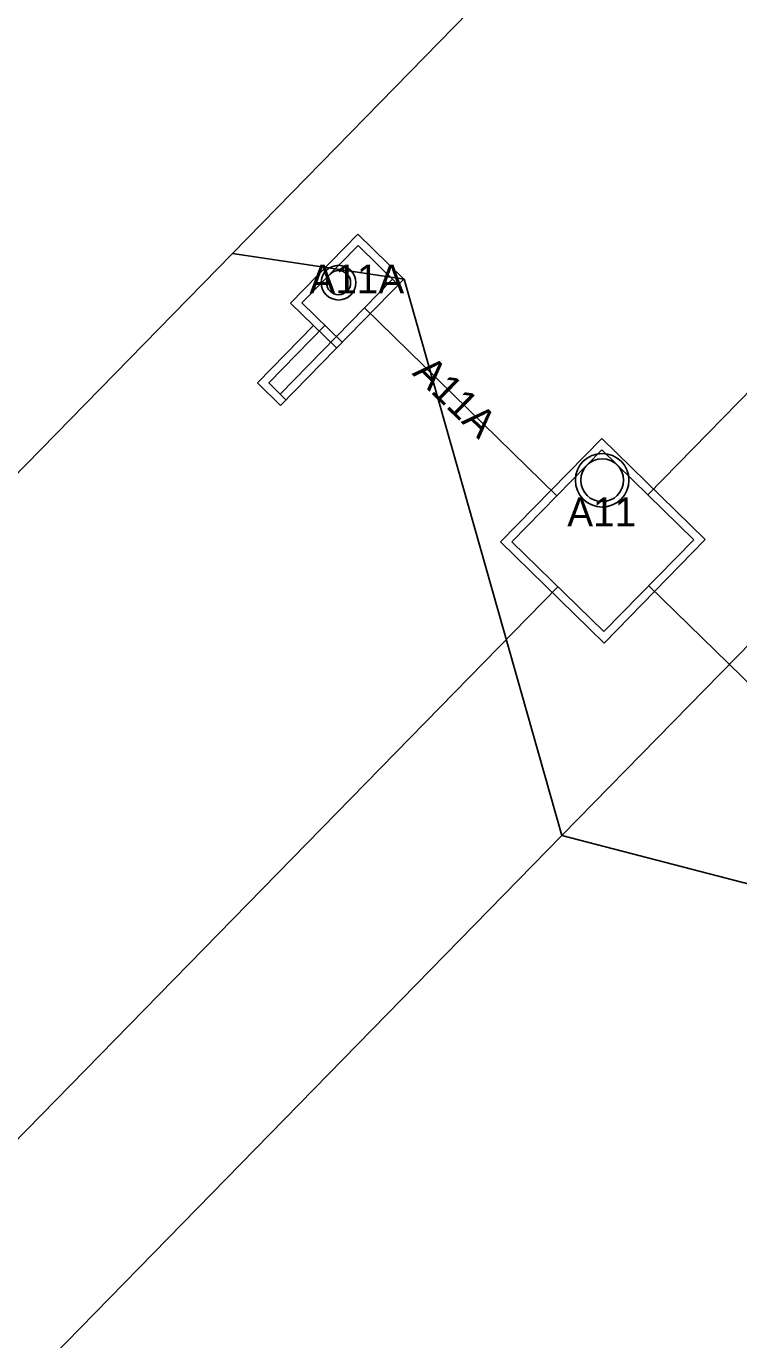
# Model space of a CAD drawing. Extents: x 2252703 to 2264864, y 13787568 to 13790989.
# Drawn here: x 2253389.3 to 2253433.6, y 13789220.9 to 13789302.7 of the extents above; entities that cross this region are included whole.
import ezdxf

# ---------------------------------------------------------------- set-up
doc = ezdxf.new("R2010")
doc.units = 0
for name, color, linetype in [('D_BOXES_1', 7, 'Continuous'), ('D_DRAIN_MISC', 7, 'Continuous'), ('D_DRAIN_NOTES_1', 7, 'Continuous'), ('D_DRN_AREA_X', 7, 'Continuous'), ('D_INLET_1', 7, 'Continuous'), ('D_PIPES_1', 7, 'Continuous')]:
    doc.layers.add(name, color=color, linetype=linetype)

msp = doc.modelspace()

# ---------------------------------------------------------------- linework, layer by layer
at = {"layer": 'D_BOXES_1'}
for p, q in [((2253427.938, 13789273.484), (2253562.133, 13789410.8)), ((2253067.974, 13788905.308), (2253422.346, 13789267.762))]:
    msp.add_line(p, q, dxfattribs=at)
at = {"layer": 'D_DRAIN_MISC'}
for p, q in [((2253410.977, 13789287.962), (2253410.977, 13789287.962)), ((2253408.156, 13789287.223), (2253408.156, 13789287.223)), ((2253409.229, 13789286.174), (2253409.229, 13789286.174)), ((2253407.482, 13789284.386), (2253407.482, 13789284.386)), ((2253410.302, 13789285.126), (2253410.302, 13789285.126)), ((2253422.281, 13789273.419), (2253422.281, 13789273.419)), ((2253427.938, 13789273.484), (2253427.938, 13789273.484)), ((2253425.142, 13789270.623), (2253425.142, 13789270.623)), ((2253422.346, 13789267.762), (2253422.346, 13789267.762)), ((2253428.003, 13789267.827), (2253428.003, 13789267.827))]:
    msp.add_line(p, q, dxfattribs=at)
at = {"layer": 'D_DRN_AREA_X'}
for p, q in [((2253542.833, 13789432.544), (2253402.086, 13789288.523)), ((2253402.086, 13789288.523), (2253375.066, 13789260.874)), ((2253402.086, 13789288.523), (2253412.771, 13789286.907)), ((2253412.771, 13789286.907), (2253402.086, 13789288.523)), ((2253412.771, 13789286.907), (2253422.582, 13789252.265)), ((2253422.582, 13789252.265), (2253412.771, 13789286.907)), ((2253422.582, 13789252.265), (2253455.781, 13789286.236)), ((2253455.781, 13789286.236), (2253422.582, 13789252.265)), ((2253390.797, 13789219.741), (2253422.582, 13789252.265)), ((2253422.582, 13789252.265), (2253390.797, 13789219.741)), ((2253422.582, 13789252.265), (2253457.441, 13789243.253)), ((2253457.441, 13789243.253), (2253422.582, 13789252.265))]:
    msp.add_line(p, q, dxfattribs=at)
at = {"layer": 'D_INLET_1'}
for p, q in [((2253405.702, 13789285.427), (2253409.896, 13789289.718)), ((2253409.896, 13789289.718), (2253412.756, 13789286.922)), ((2253406.409, 13789285.435), (2253409.904, 13789289.011)), ((2253409.904, 13789289.011), (2253412.407, 13789286.564)), ((2253405.06, 13789279.762), (2253412.049, 13789286.914)), ((2253405.068, 13789279.055), (2253412.756, 13789286.922)), ((2253405.702, 13789285.427), (2253407.132, 13789284.029)), ((2253406.409, 13789285.435), (2253408.912, 13789282.988)), ((2253403.638, 13789280.453), (2253407.132, 13789284.029)), ((2253404.345, 13789280.461), (2253407.84, 13789284.037)), ((2253407.132, 13789284.029), (2253408.563, 13789282.631)), ((2253403.638, 13789280.453), (2253405.068, 13789279.055)), ((2253404.345, 13789280.461), (2253405.418, 13789279.412)), ((2253418.779, 13789270.55), (2253425.069, 13789276.987)), ((2253425.069, 13789276.987), (2253431.506, 13789270.696)), ((2253419.486, 13789270.558), (2253425.077, 13789276.28)), ((2253425.077, 13789276.28), (2253430.799, 13789270.688)), ((2253425.215, 13789264.26), (2253418.779, 13789270.55)), ((2253425.207, 13789264.967), (2253419.486, 13789270.558)), ((2253430.799, 13789270.688), (2253425.207, 13789264.967)), ((2253431.506, 13789270.696), (2253425.215, 13789264.26))]:
    msp.add_line(p, q, dxfattribs=at)
for centre, radius in [((2253408.693, 13789286.698), 1.08), ((2253408.693, 13789286.698), 0.75), ((2253425.099, 13789274.395), 1.666), ((2253425.099, 13789274.395), 1.333)]:
    msp.add_circle(centre, radius, dxfattribs=at)
at = {"layer": 'D_PIPES_1'}
for p, q in [((2253410.302, 13789285.126), (2253422.281, 13789273.419)), ((2253455.717, 13789240.744), (2253428.003, 13789267.827))]:
    msp.add_line(p, q, dxfattribs=at)

# ---------------------------------------------------------------- texts
at = {"layer": 'D_DRAIN_NOTES_1'}
for s, p in [('A11A', (2253406.887, 13789286.026)), ('A11', (2253422.928, 13789271.523))]:
    msp.add_text(s, height=1.8, dxfattribs=at).set_placement(p)
msp.add_text('A11A', height=1.8, rotation=315.65877, dxfattribs=at).set_placement((2253413.22, 13789281.015))

doc.saveas('drawing.dxf')
